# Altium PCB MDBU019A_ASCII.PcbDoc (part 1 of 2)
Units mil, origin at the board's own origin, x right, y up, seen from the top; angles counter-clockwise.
Board outline 2500 x 2300 mil, 2 copper layers (Top Layer, Bottom Layer), stack 62 mil thick; 48 components, 19 nets, 113 pads, 75 vias.
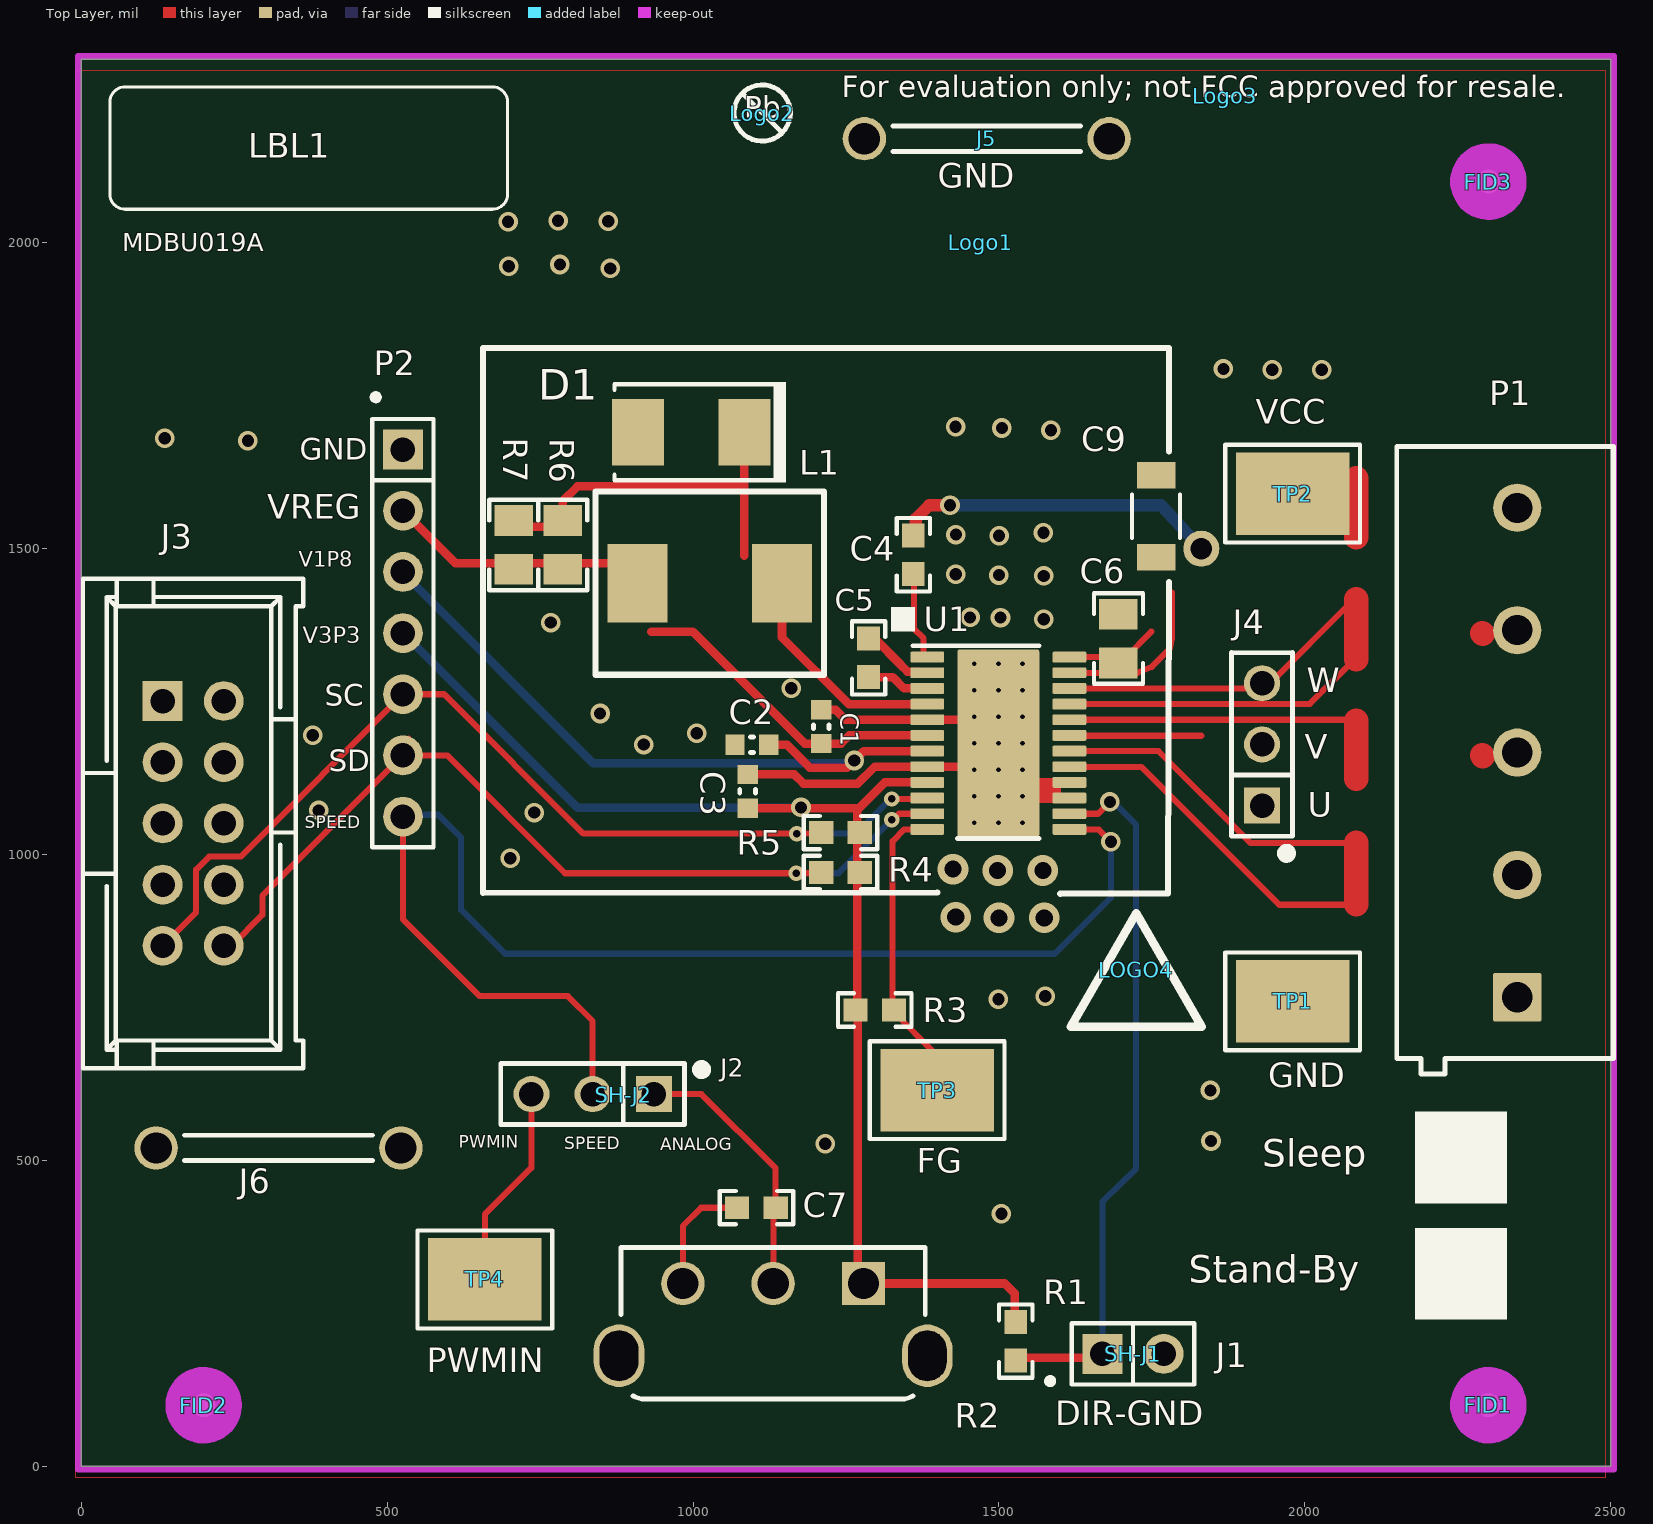
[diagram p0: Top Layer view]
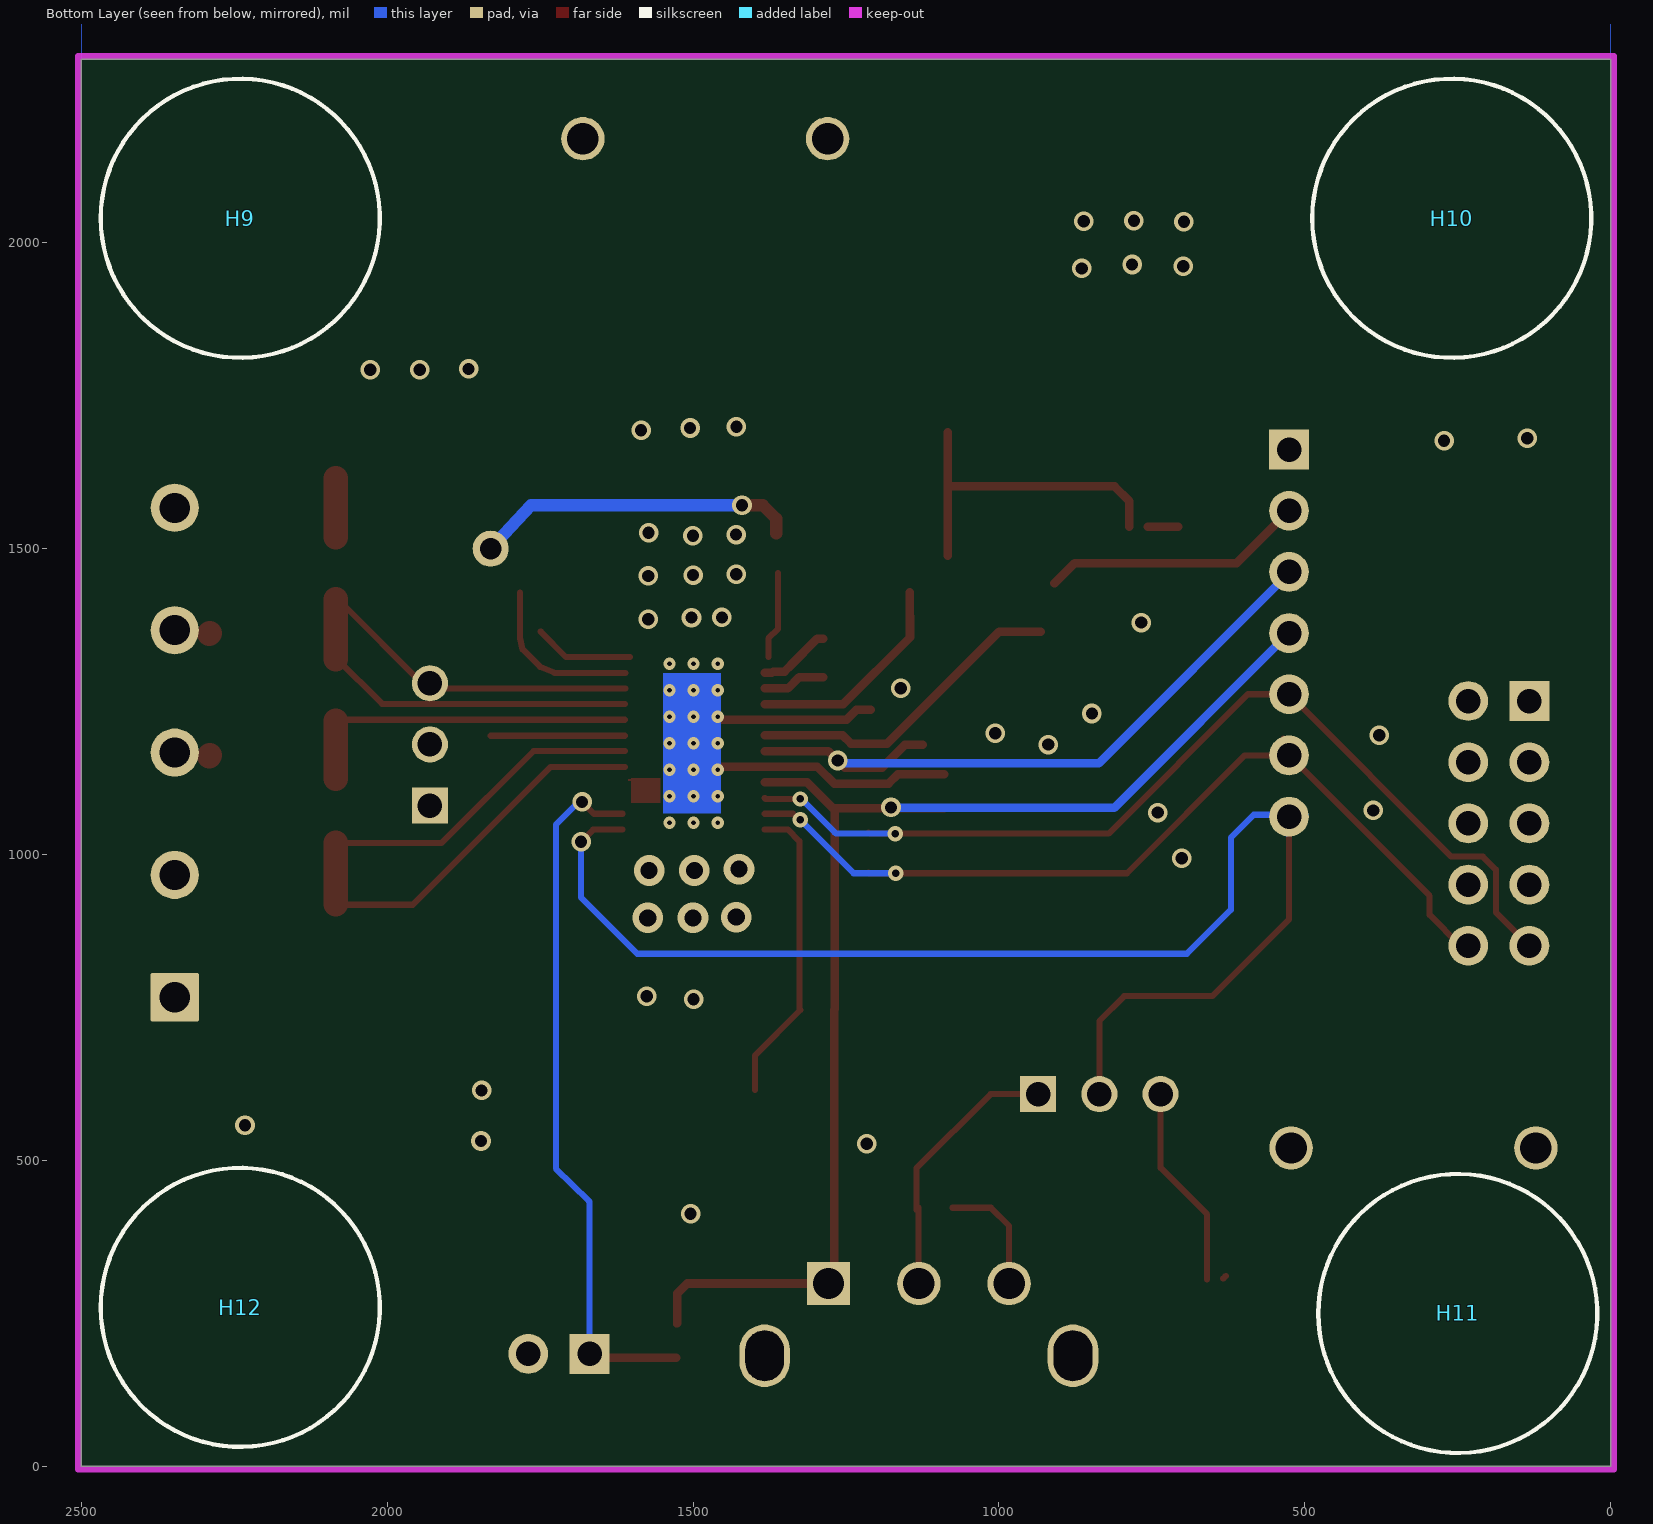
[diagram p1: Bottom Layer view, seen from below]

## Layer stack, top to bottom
Top Solder: solder mask 0.4, Solder Resist, Dk 3.5
Top Layer: signal copper 1.4
Dielectric1: core 59.2, FR-4, Dk 4.8
Bottom Layer: signal copper 1.4
Bottom Solder: solder mask 0.4, Solder Resist, Dk 3.5

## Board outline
0,0 0,2300 2500,2300 2500,0

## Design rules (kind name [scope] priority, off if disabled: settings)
AcuteAngle [All] p0: scope1count=1 scope1_0_kind=Board scope1_0_value=Board scope2count=1 scope2_0_kind=Board scope2_0_value=Board commentlength=0 minimum=4.50000000000000E+0001
AcuteAngle [All] p1: minimum=4.50000000000000E+0001 checktracksonly=FALSE
AssemblyTestPointUsage [All] p0: scope1count=1 scope1_0_kind=Board scope1_0_value=Board scope2count=1 scope2_0_kind=Board scope2_0_value=Board commentlength=0
AssemblyTestPointUsage [All] p1: valid=2
AssemblyTestpoint [All] p0: scope1count=1 scope1_0_kind=Board scope1_0_value=Board scope2count=1 scope2_0_kind=Board scope2_0_value=Board commentlength=0
Clearance Clearance_Keepouts [All] p0 off: scope1count=1 scope1_0_kind=Board scope1_0_value=Board scope2count=1 scope2_0_kind=Board scope2_0_value=Board commentlength=99 gap=0 // Protel DXP Scope 2 Expression Was: ((IsTrack Or IsArc) And Not InPoly) And IsFree and IsKeepOut
Clearance Clearance_Poly [All] p0 off: scope1count=1 scope1_0_kind=Board scope1_0_value=Board scope2count=1 scope2_0_kind=Board scope2_0_value=Board commentlength=48 gap=25 // Protel DXP Scope 1 Expression Was: InPolygon
Clearance Clearance_BoardEdge [All] p0 off: scope1count=1 scope1_0_kind=Board scope1_0_value=Board scope2count=1 scope2_0_kind=Board scope2_0_value=Board commentlength=48 gap=75 // Protel DXP Scope 2 Expression Was: IsKeepOut
Clearance Clearance_BoardEdge_Poly [All] p0 off: scope1count=1 scope1_0_kind=Board scope1_0_value=Board scope2count=1 scope2_0_kind=Board scope2_0_value=Board commentlength=48 gap=20 // Protel DXP Scope 2 Expression Was: IsKeepOut
Clearance Clearance_BoardEdge_MountingHoles [All] p0 off: scope1count=1 scope1_0_kind=Board scope1_0_value=Board scope2count=1 scope2_0_kind=Board scope2_0_value=Board commentlength=48 gap=40 // Protel DXP Scope 2 Expression Was: IsKeepOut
Clearance [All] p0: scope1count=1 scope1_0_kind=Board scope1_0_value=Board scope2count=1 scope2_0_kind=Board scope2_0_value=Board commentlength=0 gap=7.84
Clearance Clearance_Keepouts [((IsTrack Or IsArc) And Not InPoly) And IsFree and IsKeepOut vs ((IsTrack Or IsArc) And Not InPoly) And IsFree and IsKeepOut] p1: gap=0
Clearance Clearance_BoardEdge_MountingHoles [OnCopper and InComponentClass('Mounting Holes') vs IsKeepOut] p2: gap=40
Clearance Clearance_BoardEdge_Poly [OnCopper and InPoly vs IsKeepOut] p3: gap=20
Clearance Clearance_BoardEdge [OnCopper and Not InComponentClass('Logo') and not InComponentClass('FiducialMark') and not InRegion(1000,500,4000,800) and Not IsKeepout vs IsKeepOut] p4: gap=75
Clearance Clearance_Poly [InPolygon] p5: gap=25
Clearance [All] p6: gap=7.84
ComponentClearance ComponentClearance_NetTies [All] p0: scope1count=1 scope1_0_kind=ComponentClass scope1_0_value=NetTies scope2count=1 scope2_0_kind=Board scope2_0_value=Board commentlength=0 gap=0 collisioncheckmode=3
ComponentClearance ComponentClearance_THtoTH [All] p0 off: scope1count=1 scope1_0_kind=Board scope1_0_value=Board scope2count=1 scope2_0_kind=Board scope2_0_value=Board commentlength=54 gap=118.11 collisioncheckmode=3 // Protel DXP Scope 2 Expression Was: IsThruComponent
ComponentClearance ComponentClearance_THtoSMT [All] p0 off: scope1count=1 scope1_0_kind=Board scope1_0_value=Board scope2count=1 scope2_0_kind=Board scope2_0_value=Board commentlength=53 gap=100 collisioncheckmode=3 // Protel DXP Scope 2 Expression Was: IsSMTComponent
ComponentClearance ComponentClearance_SmallPassives [All] p0 off: scope1count=1 scope1_0_kind=Board scope1_0_value=Board scope2count=1 scope2_0_kind=Board scope2_0_value=Board commentlength=508 gap=20 collisioncheckmode=3 // Protel DXP Scope 2 Expression Was: HasFootprint('0201*') or HasFootprint('0402*') or HasFootprint('0508') or HasFootprint('0603*') or HasFootprint('0612') or HasFootprint('0805*') or HasFootprint('0815*') or HasFootprint('0830*') or HasFootprint('1206*') or HasFootprint('1210*') or HasFootprint('1808*') or HasFootprint('1812*') or HasFootprint('1825*') or HasFootprint('2010*') or HasFootprint('2220*') or HasFootprint('2225*') or HasFootprint('2512*') or HasFootprint('2728*') or HasFootprint('3518*')
ComponentClearance ComponentClearance_MountingHoles [All] p0: scope1count=1 scope1_0_kind=ComponentClass scope1_0_value="Mounting Holes" scope2count=1 scope2_0_kind=Board scope2_0_value=Board commentlength=0 gap=250 collisioncheckmode=3
ComponentClearance ComponentClearance_ScrewToNut [All] p0 off: scope1count=1 scope1_0_kind=Board scope1_0_value=Board scope2count=1 scope2_0_kind=Board scope2_0_value=Board commentlength=71 gap=5 collisioncheckmode=3 // Protel DXP Scope 2 Expression Was: (HasFootprint('Keystone_1902C'))
ComponentClearance ComponentClearance_Logo [All] p0: scope1count=1 scope1_0_kind=ComponentClass scope1_0_value=Logo scope2count=1 scope2_0_kind=Board scope2_0_value=Board commentlength=0 gap=50 collisioncheckmode=3
ComponentClearance ComponentClearance_Shunt [All] p0: scope1count=1 scope1_0_kind=ComponentClass scope1_0_value=Header scope2count=1 scope2_0_kind=ComponentClass scope2_0_value=Shunt commentlength=0 gap=0 collisioncheckmode=3
ComponentClearance ComponentClearance_1 [All] p0: scope1count=1 scope1_0_kind=Board scope1_0_value=Board scope2count=1 scope2_0_kind=Board scope2_0_value=Board commentlength=0 gap=10 collisioncheckmode=3
ComponentClearance ComponentClearance_NetTies [InComponentClass('NetTies')] p1: gap=0 collisioncheckmode=3 verticalgap=0 showdistances=FALSE
ComponentClearance ComponentClearance_Shunt [InComponentClass('Header') vs InComponentClass('Shunt')] p2: gap=0 collisioncheckmode=3 verticalgap=0 showdistances=FALSE
ComponentClearance ComponentClearance_1 [All] p3: gap=10 collisioncheckmode=3 verticalgap=10 showdistances=FALSE
ComponentClearance ComponentClearance_Logo [InComponentClass('Logo')] p4: gap=50 collisioncheckmode=3 verticalgap=10 showdistances=FALSE
ComponentClearance ComponentClearance_ScrewToNut [(HasFootprint('NY PMS 440 0025 PH')) vs (HasFootprint('Keystone_1902C'))] p5: gap=5 collisioncheckmode=3 verticalgap=10 showdistances=FALSE
ComponentClearance ComponentClearance_MountingHoles [InComponentClass('Mounting Holes')] p6: gap=250 collisioncheckmode=3 verticalgap=100000 showdistances=FALSE
ComponentClearance ComponentClearance_SmallPassives [HasFootprint('0201*') or HasFootprint('0402*') or HasFootprint('0508') or HasFootprint('0603*') or HasFootprint('0612') or HasFootprint('0805*') or HasFootprint('0815*') or HasFootprint('0830*') or HasFootprint('1206*') or HasFootprint('1210*') or HasFootprint('1808*') or HasFootprint('1812*') or HasFootprint('1825*') or HasFootprint('2010*') or HasFootprint('2220*') or HasFootprint('2225*') or HasFootprint('2512*') or HasFootprint('2728*') or HasFootprint('3518*') vs HasFootprint('0201*') or HasFootprint('0402*') or HasFootprint('0508') or HasFootprint('0603*') or HasFootprint('0612') or HasFootprint('0805*') or HasFootprint('0815*') or HasFootprint('0830*') or HasFootprint('1206*') or HasFootprint('1210*') or HasFootprint('1808*') or HasFootprint('1812*') or HasFootprint('1825*') or HasFootprint('2010*') or HasFootprint('2220*') or HasFootprint('2225*') or HasFootprint('2512*') or HasFootprint('2728*') or HasFootprint('3518*')] p7: gap=20 collisioncheckmode=3 verticalgap=10 showdistances=FALSE
ComponentClearance ComponentClearance_THtoSMT [IsThruComponent vs IsSMTComponent] p8: gap=100 collisioncheckmode=3 verticalgap=30 showdistances=FALSE
ComponentClearance ComponentClearance_THtoTH [IsThruComponent vs IsThruComponent] p9: gap=118.11 collisioncheckmode=3 verticalgap=30 showdistances=FALSE
DiffPairsRouting [All] p0: scope1count=1 scope1_0_kind=Board scope1_0_value=Board scope2count=1 scope2_0_kind=Board scope2_0_value=Board commentlength=0
DiffPairsRouting [All] p1: maxlimit=100 minlimit=10 mostfreqgap=10 toplayer_minwidth=15 toplayer_maxwidth=15 toplayer_prefwidth=15 bottomlayer_minwidth=15 bottomlayer_maxwidth=15 bottomlayer_prefwidth=15 maxuncoupledlength=1000
FabricationTestPointUsage TestPointUsage [All] p0: scope1count=1 scope1_0_kind=Board scope1_0_value=Board scope2count=1 scope2_0_kind=Board scope2_0_value=Board commentlength=0 valid=2 allowmultiple=FALSE
FabricationTestPointUsage TestPointUsage [All] p1: valid=2 allowmultiple=FALSE
FabricationTestpoint Testpoint [All] p0: scope1count=1 scope1_0_kind=Board scope1_0_value=Board scope2count=1 scope2_0_kind=Board scope2_0_value=Board commentlength=0 side=3 testpointundercomponent=TRUE minsize=40 maxsize=100 preferedsize=60 minholesize=0 maxholesize=40 preferedholesize=32 testpointgrid=1
FabricationTestpoint Testpoint [All] p1: side=3 testpointundercomponent=TRUE minsize=40 maxsize=100 preferedsize=60 minholesize=0 maxholesize=40 preferedholesize=32 testpointgrid=1 allowsidetop=TRUE allowsidebottom=TRUE usegrid=TRUE gridtolerance=0.01
FanoutControl Fanout_Small [All] p0 off: scope1count=1 scope1_0_kind=Board scope1_0_value=Board scope2count=1 scope2_0_kind=Board scope2_0_value=Board commentlength=84 // Protel DXP Scope 1 Expression Was: (CompPinCount < 5)   Fanout_Small (Default Rule)
FanoutControl Fanout_Default [All] p0: scope1count=1 scope1_0_kind=Board scope1_0_value=Board scope2count=1 scope2_0_kind=Board scope2_0_value=Board commentlength=30 // Fanout_Default (Default Rule)
FanoutControl Fanout_SOIC [All] p0 off: scope1count=1 scope1_0_kind=Board scope1_0_value=Board scope2count=1 scope2_0_kind=Board scope2_0_value=Board commentlength=71 // Protel DXP Scope 1 Expression Was: IsSOIC   Fanout_SOIC (Default Rule)
FanoutControl Fanout_BGA [All] p0 off: scope1count=1 scope1_0_kind=Board scope1_0_value=Board scope2count=1 scope2_0_kind=Board scope2_0_value=Board commentlength=69 // Protel DXP Scope 1 Expression Was: IsBGA   Fanout_BGA (Default Rule)
FanoutControl Fanout_LCC [All] p0 off: scope1count=1 scope1_0_kind=Board scope1_0_value=Board scope2count=1 scope2_0_kind=Board scope2_0_value=Board commentlength=69 // Protel DXP Scope 1 Expression Was: IsLCC   Fanout_LCC (Default Rule)
FanoutControl Fanout_LCC [IsLCC] p1: bgadir=Out bgaviamode=Centered fanoutstyle=Auto fanoutdirection=Alternating viagrid=1 // Fanout_LCC (Default Rule)
FanoutControl Fanout_BGA [IsBGA] p2: bgadir=Out bgaviamode=Centered fanoutstyle=Auto fanoutdirection=Alternating viagrid=1 // Fanout_BGA (Default Rule)
FanoutControl Fanout_Default [All] p4: bgadir=Out bgaviamode=Centered fanoutstyle=Auto fanoutdirection=Alternating viagrid=1 // Fanout_Default (Default Rule)
FanoutControl Fanout_Small [(CompPinCount < 5)] p5: bgadir=Out bgaviamode=Centered fanoutstyle=Auto fanoutdirection=OutThenIn viagrid=1 // Fanout_Small (Default Rule)
Height [All] p0: scope1count=1 scope1_0_kind=Board scope1_0_value=Board scope2count=1 scope2_0_kind=Board scope2_0_value=Board commentlength=0
HoleSize [All] p0: scope1count=1 scope1_0_kind=Board scope1_0_value=Board scope2count=1 scope2_0_kind=Board scope2_0_value=Board commentlength=0 absolutevalues=TRUE maxlimit=251 minlimit=7 maxpercent=80.000 minpercent=20.000
HoleSize [All] p1: absolutevalues=TRUE maxlimit=251 minlimit=7 maxpercent=80.000 minpercent=20.000
HoleToHoleClearance [All] p0: scope1count=1 scope1_0_kind=Board scope1_0_value=Board scope2count=1 scope2_0_kind=Board scope2_0_value=Board commentlength=0
LayerPairs [All] p0: scope1count=1 scope1_0_kind=Board scope1_0_value=Board scope2count=1 scope2_0_kind=Board scope2_0_value=Board commentlength=0 enforce=TRUE
MinimumAnnularRing [All] p0: scope1count=1 scope1_0_kind=Board scope1_0_value=Board scope2count=1 scope2_0_kind=Board scope2_0_value=Board commentlength=0 minimumring=6
MinimumAnnularRing MinimumAnnularRing_ThermalPadVias [All] p0 off: scope1count=1 scope1_0_kind=Board scope1_0_value=Board scope2count=1 scope2_0_kind=Board scope2_0_value=Board commentlength=63 minimumring=5.91 // Protel DXP Scope 1 Expression Was: IsVia and InAnyComponent
MinimumAnnularRing MinimumAnnularRing_ThermalPadVias [IsVia and InAnyComponent] p1: minimumring=5.91
MinimumAnnularRing [All] p2: minimumring=6
MinimumSolderMaskSliver [All] p0: scope1count=1 scope1_0_kind=Board scope1_0_value=Board scope2count=1 scope2_0_kind=Board scope2_0_value=Board commentlength=0
MinimumSolderMaskSliver MinimumSolderMaskSliver_Logo [All] p0: scope1count=1 scope1_0_kind=ComponentClass scope1_0_value=Logo scope2count=1 scope2_0_kind=ComponentClass scope2_0_value=Logo commentlength=0
MinimumSolderMaskSliver MinimumSolderMaskSliver_Logo [InComponentClass('Logo') vs InComponentClass('Logo')] p1: minsoldermaskwidth=0.7
MinimumSolderMaskSliver [All] p2: minsoldermaskwidth=3.94
NetAntennae [All] p0: scope1count=1 scope1_0_kind=Board scope1_0_value=Board scope2count=1 scope2_0_kind=Board scope2_0_value=Board commentlength=0
PasteMaskExpansion [All] p0: scope1count=1 scope1_0_kind=Board scope1_0_value=Board scope2count=1 scope2_0_kind=Board scope2_0_value=Board commentlength=0 expansion=0
PlaneClearance [All] p0: scope1count=1 scope1_0_kind=Board scope1_0_value=Board scope2count=1 scope2_0_kind=Board scope2_0_value=Board commentlength=0 clearance=20
PlaneConnect [All] p0: scope1count=1 scope1_0_kind=Board scope1_0_value=Board scope2count=1 scope2_0_kind=Board scope2_0_value=Board commentlength=0 planeconnectstyle=Relief reliefexpansion=10 reliefentries=4 reliefconductorwidth=10 reliefairgap=10
PlaneConnect [All] p1: planeconnectstyle=Relief reliefexpansion=10 reliefentries=4 reliefconductorwidth=10 reliefairgap=10
PolygonConnect PolygonConnect_5 [All] p0 off: scope1count=1 scope1_0_kind=Board scope1_0_value=Board scope2count=1 scope2_0_kind=Board scope2_0_value=Board commentlength=73 connectstyle=Direct reliefconductorwidth=10 reliefentries=4 polygonreliefangle="90 Angle" // Protel DXP Scope 2 Expression Was: IsNamedPolygon('Bottom Layer-GND')
PolygonConnect PolygonConnect_4 [All] p0 off: scope1count=1 scope1_0_kind=Board scope1_0_value=Board scope2count=1 scope2_0_kind=Board scope2_0_value=Board commentlength=70 connectstyle=Direct reliefconductorwidth=10 reliefentries=4 polygonreliefangle="90 Angle" // Protel DXP Scope 2 Expression Was: IsNamedPolygon('Top Layer-GND')
PolygonConnect PolygonConnect_3 [All] p0 off: scope1count=1 scope1_0_kind=Board scope1_0_value=Board scope2count=1 scope2_0_kind=Board scope2_0_value=Board commentlength=70 connectstyle=Direct reliefconductorwidth=10 reliefentries=4 polygonreliefangle="90 Angle" // Protel DXP Scope 2 Expression Was: IsNamedPolygon('Top Layer-GND')
PolygonConnect PolygonConnect_2 [All] p0 off: scope1count=1 scope1_0_kind=Board scope1_0_value=Board scope2count=1 scope2_0_kind=Board scope2_0_value=Board commentlength=74 connectstyle=Direct reliefconductorwidth=10 reliefentries=4 polygonreliefangle="90 Angle" // Protel DXP Scope 2 Expression Was: IsNamedPolygon('Bottom Layer-GND2')
PolygonConnect PolygonConnect_1 [All] p0 off: scope1count=1 scope1_0_kind=Board scope1_0_value=Board scope2count=1 scope2_0_kind=Board scope2_0_value=Board commentlength=71 connectstyle=Direct reliefconductorwidth=10 reliefentries=4 polygonreliefangle="90 Angle" // Protel DXP Scope 2 Expression Was: IsNamedPolygon('Top Layer-GND2')
PolygonConnect [All] p0: scope1count=1 scope1_0_kind=Board scope1_0_value=Board scope2count=1 scope2_0_kind=Board scope2_0_value=Board commentlength=0 connectstyle=Relief reliefconductorwidth=10 reliefentries=4 polygonreliefangle="90 Angle"
PolygonConnect PolygonConnect_5 [All vs IsNamedPolygon('Bottom Layer-GND')] p1: connectstyle=Direct reliefconductorwidth=10 reliefentries=4 polygonreliefangle="90 Angle" airgapwidth=10
PolygonConnect PolygonConnect_4 [All vs IsNamedPolygon('Top Layer-GND')] p2: connectstyle=Direct reliefconductorwidth=10 reliefentries=4 polygonreliefangle="90 Angle" airgapwidth=10
PolygonConnect PolygonConnect_3 [All vs IsNamedPolygon('Top Layer-GND')] p3: connectstyle=Direct reliefconductorwidth=10 reliefentries=4 polygonreliefangle="90 Angle" airgapwidth=10
PolygonConnect PolygonConnect_2 [All vs IsNamedPolygon('Bottom Layer-GND2')] p4: connectstyle=Direct reliefconductorwidth=10 reliefentries=4 polygonreliefangle="90 Angle" airgapwidth=10
PolygonConnect PolygonConnect_1 [All vs IsNamedPolygon('Top Layer-GND2')] p5: connectstyle=Direct reliefconductorwidth=10 reliefentries=4 polygonreliefangle="90 Angle" airgapwidth=10
PolygonConnect [All] p6: connectstyle=Relief reliefconductorwidth=10 reliefentries=4 polygonreliefangle="90 Angle" airgapwidth=10
RoutingCorners [All] p0: scope1count=1 scope1_0_kind=Board scope1_0_value=Board scope2count=1 scope2_0_kind=Board scope2_0_value=Board commentlength=0 cornerstyle=45-Degree minsetback=100 maxsetback=100
RoutingLayers [All] p0: scope1count=1 scope1_0_kind=Board scope1_0_value=Board scope2count=1 scope2_0_kind=Board scope2_0_value=Board commentlength=0 top layer=Automatic bottom layer=Automatic
RoutingPriority [All] p0: scope1count=1 scope1_0_kind=Board scope1_0_value=Board scope2count=1 scope2_0_kind=Board scope2_0_value=Board commentlength=0
RoutingTopology [All] p0: scope1count=1 scope1_0_kind=Board scope1_0_value=Board scope2count=1 scope2_0_kind=Board scope2_0_value=Board commentlength=0 topology=Shortest
RoutingVias [All] p0: scope1count=1 scope1_0_kind=Board scope1_0_value=Board scope2count=1 scope2_0_kind=Board scope2_0_value=Board commentlength=0 holewidth=16 width=34 viastyle="Through Hole" minholewidth=7.87 minwidth=19 maxholewidth=40 maxwidth=65
RoutingVias ThermalPadVias [All] p0 off: scope1count=1 scope1_0_kind=Board scope1_0_value=Board scope2count=1 scope2_0_kind=Board scope2_0_value=Board commentlength=63 holewidth=7.87 width=19.68 viastyle="Through Hole" minholewidth=7.87 minwidth=19.68 maxholewidth=12.99 maxwidth=23.62 // Protel DXP Scope 1 Expression Was: IsVia and InAnyComponent
RoutingVias [All] p1: holewidth=16 width=34 viastyle="Through Hole" minholewidth=7.87 minwidth=19 maxholewidth=40 maxwidth=65
RoutingVias ThermalPadVias [IsVia and InAnyComponent] p2: holewidth=7.87 width=19.68 viastyle="Through Hole" minholewidth=7.87 minwidth=19.68 maxholewidth=12.99 maxwidth=23.62
SMDToCorner [All] p0: scope1count=1 scope1_0_kind=Board scope1_0_value=Board scope2count=1 scope2_0_kind=Board scope2_0_value=Board commentlength=0 distance=30000
SMDToCorner [All] p1: distance=30000
ShortCircuit [All] p0: scope1count=1 scope1_0_kind=Board scope1_0_value=Board scope2count=1 scope2_0_kind=Board scope2_0_value=Board commentlength=0 allowed=FALSE
SilkToBoardRegionClearance [All] p0: scope1count=1 scope1_0_kind=Board scope1_0_value=Board scope2count=1 scope2_0_kind=Board scope2_0_value=Board commentlength=0
SilkToSilkClearance [All] p0: scope1count=1 scope1_0_kind=Board scope1_0_value=Board scope2count=1 scope2_0_kind=Board scope2_0_value=Board commentlength=0
SilkToSilkClearance SilkToSilkClearance_pblogo [All] p0 off: scope1count=1 scope1_0_kind=Board scope1_0_value=Board scope2count=1 scope2_0_kind=Board scope2_0_value=Board commentlength=120 // Protel DXP Scope 2 Expression Was: (HasFootprint('Pb-Free_Overlay_Medium') OR HasFootprint('Pb-Free_Overlay_Small'))
SilkToSilkClearance SilkToSilkClearance_pblogo [(HasFootprint('Pb-Free_Overlay_Medium') OR HasFootprint('Pb-Free_Overlay_Small')) vs (HasFootprint('Pb-Free_Overlay_Medium') OR HasFootprint('Pb-Free_Overlay_Small'))] p1: silktosilkclearance=0
SilkToSilkClearance [All] p2: silktosilkclearance=5
SilkToSolderMaskClearance SilkscreenOverComponentPads [All] p0 off: scope1count=1 scope1_0_kind=Board scope1_0_value=Board scope2count=1 scope2_0_kind=Board scope2_0_value=Board commentlength=44 // Protel DXP Scope 1 Expression Was: IsPad
SilkToSolderMaskClearance SilkscreenOverComponentPads [IsPad] p1: minsilkscreentomaskgap=5 clearancetoexposedcopper=TRUE
SolderMaskExpansion [All] p0: scope1count=1 scope1_0_kind=Board scope1_0_value=Board scope2count=1 scope2_0_kind=Board scope2_0_value=Board commentlength=0 expansion=1.97
SolderMaskExpansion [All] p1: expansion=1.97
UnRoutedNet [All] p0: scope1count=1 scope1_0_kind=Board scope1_0_value=Board scope2count=1 scope2_0_kind=Board scope2_0_value=Board commentlength=0
UnpouredPolygon [All] p0: scope1count=1 scope1_0_kind=Board scope1_0_value=Board scope2count=1 scope2_0_kind=Board scope2_0_value=Board commentlength=0
Width [All] p0: scope1count=1 scope1_0_kind=Board scope1_0_value=Board scope2count=1 scope2_0_kind=Board scope2_0_value=Board commentlength=0 maxlimit=100 minlimit=6 preferedwidth=10
Width [All] p1: maxlimit=100 minlimit=6 preferedwidth=10 checkconnectedcopper=TRUE
16 further rules are at their usual default settings.

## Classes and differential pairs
component class AssemblyNote: ZZ1 ZZ2 ZZ3 ZZ4
component class FiducialMark: FID1 FID2 FID3
component class MDBU019A_EVM_Hardware: FID1 FID2 FID3 H9 H10 H11 H12 LBL1 Logo1 Logo2 Logo3 LOGO4 SH-J1 SH-J2 ZZ1 ZZ2 ZZ3 ZZ4
component class Logo: Logo1
component class MDBU019A: C1 C2 C3 C4 C5 C6 C7 C9 D1 J1 J2 J3 J4 J5 J6 L1 P1 P2 R1 R2 R3 R4 R5 R6 R7 TP1 TP2 TP3 TP4 U1
component class Shunt: SH-J1 SH-J2
component class Header: J1 J2 J4 P2
component class Label: LBL1

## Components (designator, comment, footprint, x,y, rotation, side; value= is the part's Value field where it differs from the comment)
C1 "C1608X5R1A106M080AC" 0603L 1209.51,1209.03 r90 top
C2 "C1608X5R1E105K080AC" 0603L 1096.24,1179.45 r0 top
C3 "C1608X5R1E105K080AC" 0603L 1089.2,1103.43 r270 top
C4 "06035C104KAT2A" 0603 1360,1490 r270 top
C5 "06031C103KAT2A" 0603 1286.98,1321.53 r90 top
C6 "C2012X5R1H475K125AB" 0805_HV 1695.32,1353.14 r270 top
C7 "06035C104KAT2A" 0603 1103.64,422.9 r180 top
C9 "C3216X5R1H106K160AB" 1206_180 1756.76,1553 r90 top
D1 "VS-10BQ030HM3/5BT" SMB 996.79,1690.24 r180 top
FID1 "Fiducial" Fiducial10-30 2300,100 r90 top
FID2 "Fiducial" Fiducial10-30 200,100 r90 top
FID3 "Fiducial" Fiducial10-30 2300,2100 r90 top
H9 "SJ-5303 (CLEAR)" Bumpon_SJ5003Transparent 2240,2040 r180 bottom
H10 "SJ-5303 (CLEAR)" Bumpon_SJ5003Transparent 260,2040 r180 bottom
H11 "SJ-5303 (CLEAR)" Bumpon_SJ5003Transparent 250,250 r180 bottom
H12 "SJ-5303 (CLEAR)" Bumpon_SJ5003Transparent 2240,260 r180 bottom
J1 "90120-0122" CONN_90120-0122 1719.13,183.93 r0 top
J2 "PEC03SAAN" CONN_PEC03SAAN 835.93,608.59 r180 top
J3 "5103308-1" CONN_5103308-1 183.08,1051 r270 top
J4 "PEC03SAAN" CONN_PEC03SAAN 1930,1180 r90 top
J5 "D3082-05" Harwin_D3082-05 1480,2170 r180 top
J6 "D3082-05" Harwin_D3082-05 322.53,520.54 r180 top
L1 "DR74-470-R" DR74 1027.3,1443.61 r0 top
LBL1 "Size: 0.65\" x 0.20 \"" Label_650x200 371.95,2154.71 r0 top
Logo1 "Texas Instruments" TI_Stacked_Overlay_Small 1470,2000 r0 top
Logo2 "Pb-Free Symbol" Pb-Free_Overlay_Small 1113,2212 r0 top
Logo3 "FCC disclaimer" FCC_disclaimer 1870,2240 r0 top
LOGO4 "CAUTION HOT SURFACE" IEC_HotSurface_Small 1724.48,811.69 r0 top
P1 "ED120/5DS" On-Shore_ED120_5DS 2347.03,1166.77 r90 top
P2 "TSW-107-07-G-S" TSW-107-07-G-S 525.93,1362.05 r270 top
R1 "CRCW060310K0JNEA" 0603 1527.41,204.86 r270 top
R2 "296XD253B1N" CTS_296X 1131,299 r180 top
R3 "CRCW06034K75FKEA" 0603 1297,746 r0 top
R4 "CRCW06034K75FKEA" 0603 1241,971 r180 top
R5 "CRCW06034K75FKEA" 0603 1241,1036 r180 top
R6 "CRCW080578R7FKEA" 0805_HV 787.14,1506.04 r90 top
R7 "CRCW080578R7FKEA" 0805_HV 707.14,1506.04 r90 top
SH-J1 "969102-0000-DA" SNT-100-BK-G 1719.13,183.93 r0 top
SH-J2 "969102-0000-DA" SNT-100-BK-G 886.91,607.14 r0 top
TP1 "5016" Testpoint_Keystone_Compact 1980,760 r180 top
TP2 "5016" Testpoint_Keystone_Compact 1980,1590 r180 top
TP3 "5016" Testpoint_Keystone_Compact 1399,615 r180 top
TP4 "5016" Testpoint_Keystone_Compact 659.68,305.63 r180 top
U1 "DRV10983SQPWPRQ1" PWP0024B_N 1499,1182 r0 top
ZZ1 "This Assembly Note is for PCB labels only" AssemblyNoteLabel 188.21,3922.4 r0 top
ZZ2 "This Assembly Note will show in the PcbDoc and associated outputs" AssemblyNote 185,3829.11 r0 top
ZZ3 "This Assembly Note will show in the PcbDoc and associated outputs" AssemblyNote 185,3740.56 r0 top
ZZ4 "This Assembly Note will show in the PcbDoc and associated outputs" AssemblyNote 185,3652 r0 top

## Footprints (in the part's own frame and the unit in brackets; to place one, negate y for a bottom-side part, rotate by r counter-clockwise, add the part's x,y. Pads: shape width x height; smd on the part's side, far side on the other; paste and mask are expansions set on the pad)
0603 [mm] "0603 from SM-752 data"
  rect 1x0.95 smd: 1(-0.8,0) 2(0.8,0)
  silkscreen extent -1.52,-0.69 1.52,0.69
0603L [mm] "0603 from SM-752 data"
  rect 0.8x0.85 smd: 1(-0.7,0) 2(0.7,0)
  silkscreen extent -0.07,-0.33 0.07,0.33
0805_HV [mil] "0805 with 30mil clearance between pads"
  rect 50x63 smd: 1(-40,0) 2(40,0)
  silkscreen extent -74,-40 74,40
1206_180 [mm] "1206_180"
  rect 1.1x1.6 smd: 1(-1.7,0) 2(1.7,0)
  silkscreen extent -0.9,-1 0.9,1
AssemblyNote [mil] "Assembly Note"
AssemblyNoteLabel [mil] "Assembly Note for PCB Labels"
Bumpon_SJ5003Transparent [mil] "3M Hemispherical Bumpon transparent"
  round 1 on Mech4: 0(0,0)
  silkscreen extent -228,-228 228,228
CONN_90120-0122 [mm] "Molex"
  rect 1.65x1.65 hole 1.016 mask+0: 1(-1.27,0)
  round 1.65 hole 1.016 mask+0: 2(1.27,0)
  silkscreen extent -3.56,-1.27 2.54,1.27
CONN_5103308-1 [mm] "TE Connectivity (AMP) Rev E datasheet"
  rect 1.65x1.65 hole 1.016 mask+0: 1(-5.08,-1.27)
  round 1.65 hole 1.016 mask+0: 2(-5.08,1.27) 3(-2.54,-1.27) 4(-2.54,1.27) 5(0,-1.27) 6(0,1.27) 7(2.54,-1.27) 8(2.54,1.27) 9(5.08,-1.27) 10(5.08,1.27)
  silkscreen extent -10.16,-4.57 10.16,4.57
CONN_PEC03SAAN [mm] "SULLINS"
  rect 1.5x1.5 hole 1.016: 1(-2.54,0)
  round 1.5 hole 1.016: 2(0,0) 3(2.54,0)
  silkscreen extent -4.72,-1.27 3.81,1.27
CTS_296X [mm] "TH, 3-Leads, Body 6.3x12.5mm, Pitch 3.75mm"
  rect 1.8x1.8 hole 1.3: 1(-3.75,0)
  round 1.8 hole 1.3: 2(0,0) 3(3.75,0)
  oval 2.1x2.6 hole 1.6 slot 2.1 at 90 deg: MH1(-6.4,3) MH2(6.4,3)
  silkscreen extent -6.32,-1.5 6.32,4.8
DR74 [mm]
  rect 2.5x3.25 smd: 1(-3,0) 2(3,0)
  silkscreen extent -4.75,-3.8 4.75,3.8
FCC_disclaimer [mil]
Fiducial10-30 [mm]
  round 1 smd mask+0: 1(0,0)
  Top Layer keep-out circle w1.678: c0,0 r0.75
Harwin_D3082-05 [mm] "Shorting Plug, 10.16mm spacing, TH"
  round 1.8 hole 1.3: 1(-5.08,0) 2(5.08,0)
  silkscreen extent -3.9,-0.53 3.9,0.53
IEC_HotSurface_Small [mil]
  silkscreen extent -107,-93 107,92
Label_650x200 [mil] "Thermal Transfer Label"
  round 1 on Mech13: 0(0,0)
  silkscreen extent -325,-100 325,100
On-Shore_ED120_5DS [mm] "TH, 5-Leads, Body 25.4x9mm, Pitch 5.08mm"
  rrect5% 2x2 hole 1.25: 1(-10.16,0)
  round 2 hole 1.25: 2(-5.08,0) 3(0,0) 4(5.08,0) 5(10.16,0)
  silkscreen extent -13.34,-4 12.7,5
Pb-Free_Overlay_Small [mil]
  silkscreen extent -46,-46 46,46
PWP0024B_N [mm] "TSOP, 24-Leads, Body 7.9x4.5mm (max), Pitch 0.65mm, IPC Medium Density"
  rrect22% 1.4x0.45 smd: 1(-2.95,3.575) 2(-2.95,2.925) 3(-2.95,2.275) 4(-2.95,1.625) 5(-2.95,0.975) 6(-2.95,0.325) 7(-2.95,-0.325) 8(-2.95,-0.975) 9(-2.95,-1.625) 10(-2.95,-2.275) 11(-2.95,-2.925) 12(-2.95,-3.575) 13(2.95,-3.575) 14(2.95,-2.925) 15(2.95,-2.275) 16(2.95,-1.625) 17(2.95,-0.975) 18(2.95,-0.325) 19(2.95,0.325) 20(2.95,0.975) 21(2.95,1.625) 22(2.95,2.275) 23(2.95,2.925) 24(2.95,3.575)
  rrect6% 3.4x7.8 smd paste-2 mask+0: 25(0,0)
  rrect4% 2.4x5.16 on Top Paste: 25(0,0)
  rrect4% 2.4x5.16 on Top Solder: 25(0,0)
  silkscreen extent -3.55,-3.95 1.7,4.05
SMB [mil] "Molded Diode, 2-Leads, Body 5.4x3.6mm, IPC Medium Density, based on OnSemi component dimensions"
  rect 85x107.99 smd: 1(-87.01,0) 2(87.01,0)
  silkscreen extent -155,-82 125,82
SNT-100-BK-G [mil] "Samtec STEP model"
  round 1 on Mech3: 0(0,0)
Testpoint_Keystone_Compact [mil] "Compact SMT test point"
  rect 185x135 smd: 1(0,0)
  silkscreen extent -110,-80 110,80
TI_Stacked_Overlay_Small [mil]
TSW-107-07-G-S [mm] "Samtec 100mil, 1x7, 230 mil above insulator"
  rect 1.65x1.65 hole 1.016 mask+0: 1(-7.62,0)
  round 1.65 hole 1.016 mask+0: 2(-5.08,0) 3(-2.54,0) 4(0,0) 5(2.54,0) 6(5.08,0) 7(7.62,0)
  silkscreen extent -9.91,-1.27 8.89,1.27

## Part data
C1: "CAP, CERM, 10 µF, 10 V, +/- 20%, X5R, 0603"
C2 C3: "CAP, CERM, 1 µF, 25 V, +/- 10%, X5R, 0603"
C4 C7: "CAP, CERM, 0.1 µF, 50 V, +/- 10%, X7R, 0603"
C5: "CAP, CERM, 0.01 µF, 100 V, +/- 10%, X7R, 0603"
C6: "CAP, CERM, 4.7 µF, 50 V, +/- 10%, X5R, 0805"
C9: "CAP, CERM, 10 µF, 50 V, +/- 10%, X5R, 1206"
D1: "Diode, Schottky, 30 V, 1 A, AEC-Q101, SMB"
FID1 FID2 FID3: "Fiducial mark.  There is nothing to buy or mount."
H9 H10 H11 H12: "Bumpon, Hemisphere, 0.44 X 0.20, Clear"
J1: "Header, 100mil, 2x1, Tin, TH"
J2 J4: "Header, 100mil, 3x1, Tin, TH"
J3: "Header (shrouded), 100mil, 5x2, Gold, TH"
J5 J6: "1mm Uninsulated Shorting Plug, 10.16mm spacing, TH"
L1: "Inductor, Shielded Drum Core, Ferrite, 47 µH, 1.15 A, 0.216 ohm, SMD"
LBL1: library part THT-14-423-10, "Thermal Transfer Printable Labels, 0.650\" W x 0.200\" H - 10,000 per roll"
Logo1: library part TI_Logo, "Texas Instrument Corporate Signature"
Logo2: library part Pb-Free
Logo3: library part FCC_disclaimer, "FCC_disclaimer"
LOGO4: library part IEC_HotSurface, "IEC 61010-1 Hot Surface Warning"
P1: "Terminal Block, 5.08 mm, 5x1, Brass, TH"
P2: "Header, 100mil, 7x1, Gold, TH"
R1: "RES, 10 k, 5%, 0.1 W, 0603"
R2: "Trimmer, 25k ohm, 0.15W, TH"
R3 R4 R5: "RES, 4.75 k, 1%, 0.1 W, 0603"
R6 R7: "RES, 78.7, 1%, 0.125 W, 0805"
SH-J1 SH-J2: "Shunt, 100mil, Gold plated, Black"
TP1 TP2 TP3 TP4: "Test Point, Compact, SMT"
U1: "Industrial, Three-Phase, Sensorless BLDC Motor Driver, PWP0024B (TSSOP-24)"
ZZ1: library part AssemblyNoteLabel
ZZ2 ZZ3 ZZ4: library part AssemblyNote

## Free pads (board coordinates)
  round 59.06 hole 35.43: 0(1830.74,1500)

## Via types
v1: diameter 32, hole 20, Top Layer to Bottom Layer, 44 vias
v2: diameter 19.68, hole 7.87, Top Layer to Bottom Layer, 15 vias
v3: diameter 19.68, hole 7.87, Top Layer to Bottom Layer, tented both sides, 6 vias
v4: diameter 50, hole 28, Top Layer to Bottom Layer, 6 vias
v5: diameter 25, hole 12, Top Layer to Bottom Layer, 4 vias

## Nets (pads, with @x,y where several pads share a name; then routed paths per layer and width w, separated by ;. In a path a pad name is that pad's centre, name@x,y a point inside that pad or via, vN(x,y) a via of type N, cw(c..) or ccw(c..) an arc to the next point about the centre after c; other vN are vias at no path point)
CPN: C5.1 U1.3 | length 103.5
  Top Layer w14: C5.1@1286.98,1290.03 1326.47,1290.03 1344.94,1271.57 U1.3@1382.86,1271.57
CPP: C5.2 U1.2 | length 119.4
  Top Layer w14: C5.2@1286.98,1353.02 1297.03,1353.02 1340.46,1309.6 1340.46,1308.88 1350.29,1299.05 1369.11,1299.05 1371,1297.16 U1.2@1382.86,1297.16
DIR: J1.1 R1.2 U1.14 | length 1173.8
  Top Layer w10: U1.14@1615.14,1066.84 1662.04,1066.84 v1(1681.36,1086.17) ; J1.1@1662.5,177.3 J1.1@1669.13,183.93
  Top Layer w14: R1.2@1527.41,177.3 J1.1@1662.5,177.3
  Bottom Layer w10: J1.1@1669.13,183.93 1669.13,432.63 1670.65,434.15 1724.1,486.68 1724.1,1049.08 1687.02,1086.17 v1(1681.36,1086.17) 1681.36,1078.95 v1@1680.23,1077.81
FG: R3.2 TP3.1 U1.12 | length 503.2
  Top Layer w10: U1.12@1382.86,1041.25 1345.28,1041.25 1326.03,1022 1326.03,747.47 1324.56,746 1399,671.56 TP3.1@1399,615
